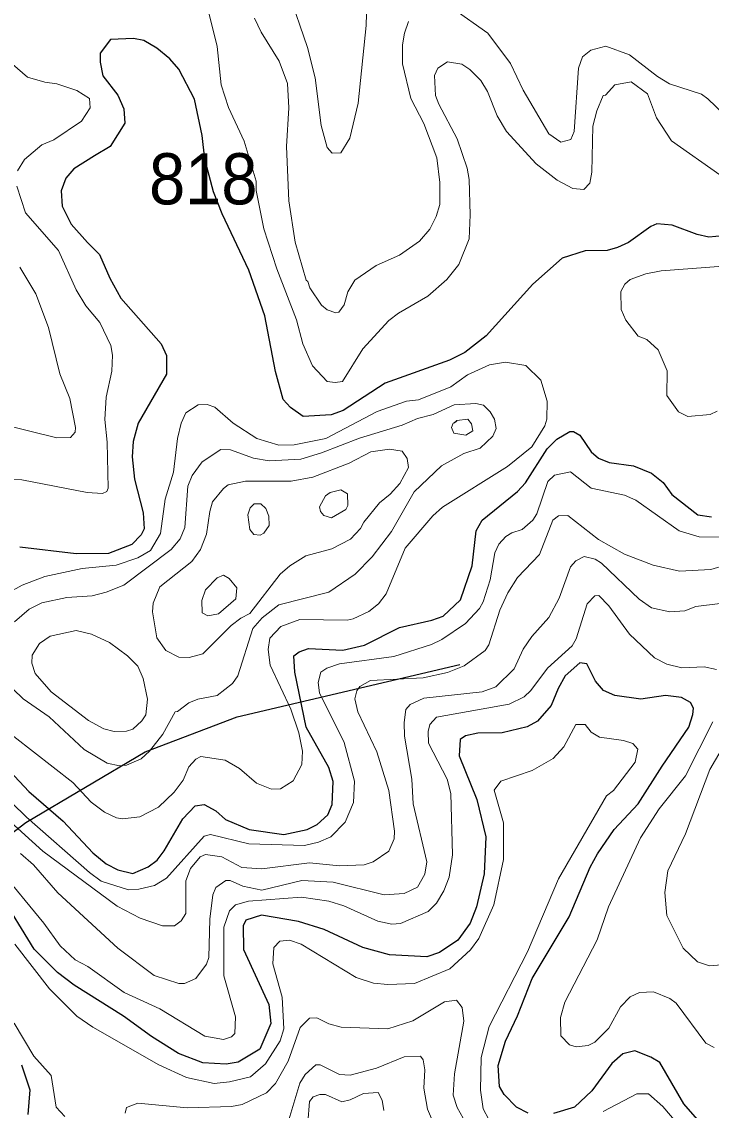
# Model space of a CAD drawing. Extents: x 673.3 to 698.5, y 6984.3 to 7012.3.
# Drawn here: x 679.596 to 680.675, y 6996.068 to 6997.77 of the extents above; entities that cross this region are included whole.
import ezdxf

# ---------------------------------------------------------------- set-up
doc = ezdxf.new("R2010")
doc.units = 0
doc.header["$LTSCALE"] = 0.032
for name, color, linetype, lineweight in [('1', 7, 'Continuous', 25), ('2', 7, 'Continuous', 13), ('26', 7, 'Continuous', 25)]:
    doc.layers.add(name, color=color, linetype=linetype, lineweight=lineweight)
doc.layers.add('21', color=7, linetype='Continuous')

msp = doc.modelspace()

# ---------------------------------------------------------------- linework, layer by layer
at = {"layer": '1'}
for points in [[(680.7042, 6997.4363), (680.6712, 6997.4331), (680.653, 6997.4373), (680.6137, 6997.4523), (680.59, 6997.4541), (680.5803, 6997.4501), (680.5455, 6997.425), (680.5285, 6997.4169), (680.5122, 6997.4127), (680.4777, 6997.4118), (680.4419, 6997.4004), (680.3957, 6997.36), (680.3227, 6997.2788), (680.2892, 6997.2527), (680.2656, 6997.241), (680.165, 6997.2049), (680.0989, 6997.1622), (680.0803, 6997.1553), (680.0363, 6997.1529), (680.0168, 6997.1668), (680.0053, 6997.1792), (679.9932, 6997.2234), (679.9767, 6997.3103), (679.9516, 6997.3817), (679.9099, 6997.4699), (679.8962, 6997.5041), (679.8829, 6997.5553), (679.8783, 6997.5921), (679.8664, 6997.6489), (679.8422, 6997.6963), (679.828, 6997.712), (679.8073, 6997.7289), (679.7871, 6997.7408), (679.7711, 6997.7441), (679.7353, 6997.7424), (679.719, 6997.7212), (679.7187, 6997.7071), (679.7229, 6997.6854), (679.7467, 6997.6554), (679.7561, 6997.6338), (679.7577, 6997.6116), (679.7345, 6997.5751), (679.7101, 6997.5605), (679.6775, 6997.5402), (679.665, 6997.5256), (679.6577, 6997.5057), (679.6597, 6997.4817), (679.6735, 6997.4536), (679.699, 6997.425), (679.718, 6997.4061)], [(679.718, 6997.4061), (679.734, 6997.369), (679.7511, 6997.3378), (679.8145, 6997.2663), (679.8229, 6997.2481), (679.8227, 6997.2191), (679.7783, 6997.1425), (679.7707, 6997.1136), (679.7692, 6997.0898), (679.7724, 6997.0546), (679.7863, 6997.0022), (679.7876, 6996.9772), (679.7828, 6996.9678), (679.7682, 6996.9527), (679.7317, 6996.9387), (679.6815, 6996.9378), (679.5932, 6996.9484)], [(679.5777, 6996.5983), (679.6071, 6996.5664), (679.6611, 6996.5198), (679.7075, 6996.4701), (679.7284, 6996.4533), (679.7465, 6996.4439), (679.7698, 6996.438), (679.7939, 6996.4486), (679.8082, 6996.4588), (679.8192, 6996.4735), (679.8483, 6996.5236), (679.8675, 6996.5437), (679.8818, 6996.5459), (679.8998, 6996.5361), (679.9152, 6996.5224), (679.952, 6996.5066), (680.0063, 6996.499), (680.0425, 6996.5068), (680.0582, 6996.5144), (680.0753, 6996.5299), (680.0819, 6996.5461), (680.0832, 6996.5817), (680.0767, 6996.6038), (680.0411, 6996.6669), (680.0232, 6996.753), (680.0219, 6996.7784), (680.03, 6996.7848), (680.045, 6996.7897), (680.0985, 6996.7872), (680.1327, 6996.795), (680.187, 6996.8226), (680.2379, 6996.8341), (680.2556, 6996.8404), (680.2826, 6996.8662), (680.3009, 6996.9191), (680.3069, 6996.974), (680.3165, 6996.9908), (680.372, 6997.0357), (680.3845, 6997.0492), (680.418, 6997.1021), (680.4332, 6997.1171), (680.4535, 6997.1292), (680.4595, 6997.1292), (680.4692, 6997.1237), (680.4869, 6997.0973), (680.4986, 6997.0878), (680.5154, 6997.0811), (680.5532, 6997.0756), (680.5814, 6997.0643), (680.5998, 6997.0494), (680.6134, 6997.031), (680.6541, 6996.9988), (680.6755, 6996.9957)], [(680.3885, 6996.0632), (680.37, 6996.0726), (680.3509, 6996.0923), (680.3437, 6996.1049), (680.3417, 6996.1376), (680.3528, 6996.1757), (680.3718, 6996.2155), (680.3945, 6996.2738), (680.4526, 6996.3705), (680.4855, 6996.4477), (680.4968, 6996.4686), (680.5231, 6996.5068), (680.5604, 6996.5468), (680.5982, 6996.6057), (680.6397, 6996.6667), (680.6463, 6996.6868), (680.6469, 6996.6967), (680.6422, 6996.7054), (680.6283, 6996.7131), (680.6031, 6996.7163), (680.5648, 6996.7107), (680.5242, 6996.7166), (680.5061, 6996.7243), (680.4938, 6996.7386), (680.4803, 6996.766), (680.4693, 6996.7674), (680.4466, 6996.7471), (680.4352, 6996.7274), (680.4247, 6996.7009), (680.4031, 6996.6765), (680.3868, 6996.6676), (680.3477, 6996.6578), (680.3099, 6996.6577), (680.2905, 6996.6536), (680.2823, 6996.6476), (680.2807, 6996.6219), (680.3084, 6996.5539), (680.3221, 6996.4956), (680.3198, 6996.4373), (680.3076, 6996.386), (680.2977, 6996.3604), (680.2786, 6996.3335), (680.2499, 6996.3142), (680.2301, 6996.3076), (680.1718, 6996.3107), (680.13, 6996.3222), (680.0696, 6996.3503), (680.0291, 6996.3631), (679.9715, 6996.3726), (679.9467, 6996.3652), (679.9427, 6996.3563), (679.9434, 6996.3191), (679.9828, 6996.2332), (679.9858, 6996.2035), (679.9689, 6996.1631), (679.935, 6996.143), (679.916, 6996.1398), (679.8797, 6996.142), (679.8416, 6996.1565), (679.7991, 6996.1831), (679.7555, 6996.2151), (679.6781, 6996.2634), (679.6522, 6996.2834), (679.6158, 6996.3199), (679.5612, 6996.4071)], [(680.668, 6996.0366), (680.632, 6996.0777), (680.5945, 6996.1425), (680.5805, 6996.151), (680.5556, 6996.1609), (680.5364, 6996.156), (680.5196, 6996.1408), (680.488, 6996.098), (680.4609, 6996.0724), (680.428, 6996.0625)], [(679.5956, 6996.139), (679.6087, 6996.0998), (679.6056, 6996.0611)]]:
    msp.add_lwpolyline(points, dxfattribs=at)
at = {"layer": '2'}
for points in [[(680.1365, 6997.8202), (680.1348, 6997.7644), (680.1226, 6997.6431), (680.1093, 6997.5879), (680.0952, 6997.5652), (680.082, 6997.5646), (680.0742, 6997.5735), (680.0647, 6997.6081), (680.0551, 6997.6827), (680.0433, 6997.7297), (679.9839, 6997.9036)], [(679.8808, 6997.818), (679.902, 6997.7316), (679.9084, 6997.6717), (679.9197, 6997.636), (679.9443, 6997.5834)], [(680.7078, 6997.6133), (680.6697, 6997.6499), (680.6596, 6997.6568), (680.6095, 6997.6732), (680.5906, 6997.6845), (680.5472, 6997.7183), (680.5102, 6997.7318), (680.4864, 6997.7256), (680.4736, 6997.7154), (680.4671, 6997.6976), (680.4605, 6997.5984), (680.4555, 6997.5862), (680.4394, 6997.5821), (680.4209, 6997.5949), (680.3807, 6997.6633), (680.3609, 6997.705), (680.3252, 6997.7523), (680.2709, 6997.7911)], [(680.2015, 6997.7705), (680.1949, 6997.7524), (680.1919, 6997.7341), (680.1918, 6997.7042), (680.2049, 6997.6504), (680.2252, 6997.6113), (680.2455, 6997.5576), (680.2504, 6997.5188), (680.2504, 6997.4846), (680.2447, 6997.4658), (680.2344, 6997.4458), (680.2183, 6997.4269), (680.1872, 6997.4049), (680.1506, 6997.3891), (680.1172, 6997.3663), (680.1066, 6997.348), (680.1005, 6997.3277), (680.0923, 6997.3158), (680.0875, 6997.3149), (680.0743, 6997.3195), (680.0651, 6997.3268), (680.0469, 6997.354), (680.0439, 6997.3639), (680.041, 6997.3661), (680.0241, 6997.4254), (680.0143, 6997.4902), (680.0103, 6997.5749), (680.0143, 6997.6358), (680.0119, 6997.6734), (679.999, 6997.7088), (679.9707, 6997.7541), (679.9605, 6997.7758)], [(679.5898, 6997.5371), (679.6003, 6997.5547), (679.6274, 6997.5779), (679.6463, 6997.5854), (679.6896, 6997.6148), (679.7031, 6997.6355), (679.7023, 6997.6503), (679.6826, 6997.6627), (679.6509, 6997.6731), (679.6323, 6997.6756), (679.6052, 6997.6835), (679.5819, 6997.7041)], [(679.9443, 6997.5834), (679.9628, 6997.5207), (679.963, 6997.5063), (679.9752, 6997.4464), (679.9951, 6997.384), (680.0263, 6997.3041), (680.0361, 6997.2663), (680.051, 6997.2319), (680.0741, 6997.2077), (680.0866, 6997.2058), (680.0979, 6997.2075), (680.1298, 6997.2588), (680.1703, 6997.303), (680.1854, 6997.3145), (680.2315, 6997.3408), (680.2614, 6997.3673), (680.2801, 6997.3903), (680.296, 6997.4306), (680.2977, 6997.4684), (680.2961, 6997.5236), (680.2929, 6997.5411), (680.2772, 6997.5872), (680.2485, 6997.6411), (680.2437, 6997.6547), (680.2422, 6997.6861), (680.2474, 6997.6978), (680.2622, 6997.7074), (680.2846, 6997.7041), (680.297, 6997.6958), (680.3147, 6997.6781), (680.3248, 6997.6613), (680.34, 6997.623), (680.3545, 6997.5986), (680.4009, 6997.5479), (680.4337, 6997.5227), (680.4586, 6997.5094), (680.4757, 6997.5079), (680.485, 6997.5177), (680.4883, 6997.5351), (680.4899, 6997.6067), (680.496, 6997.6309), (680.506, 6997.6549), (680.5094, 6997.6555), (680.5242, 6997.6715), (680.5495, 6997.6764), (680.5754, 6997.6576), (680.5891, 6997.6198), (680.6125, 6997.5839), (680.6884, 6997.5308)], [(679.5422, 6997.0542), (679.5963, 6997.0535), (679.6985, 6997.034), (679.7226, 6997.0323), (679.7291, 6997.0356), (679.7312, 6997.0408), (679.73, 6997.1129), (679.726, 6997.1481), (679.7281, 6997.183), (679.7373, 6997.2238), (679.7382, 6997.2487), (679.7358, 6997.2641), (679.7182, 6997.2997), (679.6966, 6997.3261), (679.6811, 6997.351), (679.6535, 6997.4126), (679.6022, 6997.4716), (679.5884, 6997.513)], [(679.5934, 6997.3863), (679.6181, 6997.3448), (679.6381, 6997.2919), (679.6558, 6997.2194), (679.6715, 6997.1811), (679.6803, 6997.1357), (679.6796, 6997.1282), (679.6724, 6997.1202), (679.6513, 6997.1195), (679.5601, 6997.1416)], [(680.6938, 6997.3878), (680.5964, 6997.3808), (680.5724, 6997.376), (680.548, 6997.3672), (680.5396, 6997.36), (680.5333, 6997.3481), (680.5338, 6997.3201), (680.5413, 6997.3033), (680.5607, 6997.2785), (680.5743, 6997.2734), (680.592, 6997.2573), (680.6062, 6997.2243), (680.6056, 6997.1854), (680.6237, 6997.16), (680.6383, 6997.1527), (680.6732, 6997.1557), (680.6842, 6997.1613)], [(679.5838, 6996.6525), (679.6761, 6996.5805), (679.7049, 6996.5494), (679.7255, 6996.5339), (679.7447, 6996.525), (679.7539, 6996.5234), (679.7812, 6996.5265), (679.8101, 6996.542), (679.8348, 6996.5653), (679.8488, 6996.5842), (679.8574, 6996.6048), (679.8686, 6996.6169), (679.8762, 6996.621), (679.9146, 6996.6153), (679.9369, 6996.6023), (679.9636, 6996.5792), (679.9872, 6996.5698), (680.001, 6996.5706), (680.021, 6996.583), (680.0343, 6996.6086), (680.0354, 6996.6292), (680.0297, 6996.6579), (680.017, 6996.6949), (679.985, 6996.7641), (679.9817, 6996.7884), (679.9844, 6996.806), (680.0018, 6996.8244), (680.0315, 6996.8351), (680.1053, 6996.8345), (680.1146, 6996.8364), (680.1394, 6996.8478), (680.1546, 6996.86), (680.1664, 6996.8757), (680.1959, 6996.9467), (680.2392, 6996.9975), (680.2545, 6997.0108), (680.3564, 6997.0744), (680.3942, 6997.1052), (680.4145, 6997.1383), (680.4176, 6997.1487), (680.4182, 6997.1767), (680.4085, 6997.2096), (680.385, 6997.2324), (680.3532, 6997.2376), (680.3278, 6997.2334), (680.2937, 6997.2179), (680.2673, 6997.1991), (680.2171, 6997.1788), (680.1981, 6997.1769), (680.1525, 6997.1604), (680.0718, 6997.1185), (680.0223, 6997.1087), (679.9986, 6997.1081), (679.9639, 6997.1182), (679.9272, 6997.1426), (679.8981, 6997.1673), (679.8864, 6997.1715), (679.8723, 6997.171), (679.8531, 6997.1584), (679.8458, 6997.1424), (679.8401, 6997.1184), (679.8334, 6997.0655), (679.8205, 6997.0236), (679.8131, 6996.9697), (679.7974, 6996.9434), (679.7779, 6996.9316), (679.7438, 6996.9205), (679.6908, 6996.915), (679.6323, 6996.9028), (679.5968, 6996.889), (679.5724, 6996.8753)], [(679.5827, 6996.7263), (679.5987, 6996.711), (679.6393, 6996.683), (679.694, 6996.6318), (679.7301, 6996.6105), (679.7494, 6996.6064), (679.76, 6996.6073), (679.7828, 6996.6172), (679.7959, 6996.6291), (679.817, 6996.6558), (679.8364, 6996.6907), (679.84, 6996.6912), (679.8574, 6996.705), (679.8719, 6996.7106), (679.9017, 6996.7166), (679.9259, 6996.7354), (679.9345, 6996.7473), (679.958, 6996.8212), (679.9724, 6996.8381), (679.9983, 6996.858), (680.0768, 6996.8782), (680.1181, 6996.9064), (680.1442, 6996.9334), (680.1749, 6996.9731), (680.2099, 6997.0349), (680.2527, 6997.0754), (680.2879, 6997.095), (680.3134, 6997.1033), (680.3331, 6997.1218), (680.3383, 6997.1339), (680.3357, 6997.1484), (680.3288, 6997.1599), (680.3184, 6997.1704), (680.3066, 6997.1731), (680.2729, 6997.1708), (680.2397, 6997.156), (680.2154, 6997.1495), (680.1916, 6997.1391), (680.1245, 6997.1187), (680.0654, 6997.0958), (680.033, 6997.0861), (679.9835, 6997.0837), (679.9587, 6997.0875), (679.9229, 6997.1006), (679.9076, 6997.1011), (679.8784, 6997.0819), (679.8627, 6997.0606), (679.8561, 6997.0436), (679.8513, 6996.9792), (679.844, 6996.9615), (679.83, 6996.945), (679.7559, 6996.8888), (679.7284, 6996.878), (679.7064, 6996.8724), (679.6668, 6996.8695), (679.6275, 6996.8612), (679.6077, 6996.8513), (679.585, 6996.8317)], [(680.6894, 6996.9639), (680.6562, 6996.9648), (680.6247, 6996.9738), (680.557, 6997.022), (680.539, 6997.03), (680.4872, 6997.0405), (680.4548, 6997.0663), (680.4299, 6997.0609), (680.4193, 6997.0509), (680.4019, 6997.0005), (680.396, 6996.9906), (680.3793, 6996.9759), (680.3629, 6996.9708), (680.3533, 6996.9649), (680.3428, 6996.953), (680.3365, 6996.9394), (680.3293, 6996.8973), (680.3183, 6996.8627), (680.3124, 6996.8525), (680.2902, 6996.8288), (680.2532, 6996.8039), (680.2372, 6996.7963), (680.1783, 6996.7775), (680.0933, 6996.7659), (680.0735, 6996.7593), (680.0641, 6996.7529)], [(680.4064, 6996.937), (680.4272, 6996.9907), (680.4361, 6996.9973), (680.4508, 6996.9979), (680.4985, 6996.9606), (680.539, 6996.9373), (680.5843, 6996.9205), (680.6253, 6996.911), (680.6744, 6996.9133), (680.6989, 6996.9206)], [(679.5735, 6996.5235), (679.6292, 6996.4729), (679.7453, 6996.387), (679.7816, 6996.368), (679.8162, 6996.3564), (679.8351, 6996.3562), (679.8454, 6996.3642), (679.853, 6996.3752), (679.8531, 6996.4264), (679.8604, 6996.4459), (679.8755, 6996.4643), (679.8838, 6996.4679), (679.909, 6996.4639), (679.9405, 6996.4475), (679.9717, 6996.4451), (680.0466, 6996.4548), (680.0932, 6996.4501), (680.1318, 6996.4516), (680.1461, 6996.4561), (680.1705, 6996.4729), (680.1787, 6996.4925), (680.1796, 6996.5042), (680.1706, 6996.5676), (680.1517, 6996.6281), (680.1221, 6996.6911), (680.1171, 6996.7111), (680.1202, 6996.7236), (680.1253, 6996.7303), (680.142, 6996.74), (680.2241, 6996.7439), (680.2625, 6996.7523), (680.2885, 6996.7626), (680.3211, 6996.7869), (680.3267, 6996.7958), (680.3444, 6996.8498), (680.3565, 6996.8769), (680.3718, 6996.9012), (680.4064, 6996.937)], [(680.3808, 6996.7888), (680.394, 6996.8086), (680.421, 6996.8383), (680.4369, 6996.8686), (680.4549, 6996.9175), (680.4631, 6996.9272), (680.4759, 6996.9336), (680.4935, 6996.9298), (680.5034, 6996.9233), (680.5622, 6996.8673), (680.5813, 6996.8535), (680.6101, 6996.8475), (680.6337, 6996.849), (680.6507, 6996.8556), (680.6891, 6996.8604)], [(680.6832, 6996.7572), (680.664, 6996.7611), (680.6288, 6996.7595), (680.6053, 6996.7655), (680.5863, 6996.7753), (680.5469, 6996.8122), (680.5148, 6996.8567), (680.4993, 6996.8726), (680.4928, 6996.8723), (680.4806, 6996.8597), (680.4638, 6996.8052), (680.4575, 6996.7941), (680.4188, 6996.7592), (680.3926, 6996.7242), (680.382, 6996.7142), (680.3586, 6996.7028), (680.2452, 6996.6826), (680.2349, 6996.6713), (680.2318, 6996.6601), (680.2326, 6996.6418), (680.2617, 6996.5855), (680.2674, 6996.5631), (680.2701, 6996.4674), (680.2651, 6996.4321), (680.2568, 6996.4107), (680.2449, 6996.3917), (680.2319, 6996.3785), (680.1888, 6996.36), (680.1751, 6996.359), (680.1535, 6996.3637), (680.1001, 6996.3872), (680.0767, 6996.3947), (680.0339, 6996.4012), (679.951, 6996.3945), (679.9308, 6996.389), (679.921, 6996.3795), (679.9124, 6996.3543), (679.9125, 6996.2779), (679.9304, 6996.2138), (679.9295, 6996.1879), (679.9246, 6996.1823), (679.9116, 6996.1782), (679.8824, 6996.1834), (679.812, 6996.2262), (679.7567, 6996.2518), (679.6997, 6996.2924), (679.6798, 6996.3031), (679.6565, 6996.3249), (679.6309, 6996.3602), (679.56, 6996.4457)], [(679.5943, 6996.4691), (679.6146, 6996.4514), (679.6526, 6996.4077), (679.7466, 6996.3211), (679.8032, 6996.2783), (679.8418, 6996.2661), (679.851, 6996.266), (679.8688, 6996.2737), (679.8853, 6996.2961), (679.8888, 6996.3067), (679.8906, 6996.3664), (679.8951, 6996.4049), (679.8998, 6996.4162), (679.9155, 6996.427), (679.9223, 6996.4272), (679.9421, 6996.4182), (679.9716, 6996.4118), (680.0343, 6996.4272), (680.0835, 6996.4247), (680.163, 6996.4045), (680.1946, 6996.4069), (680.2156, 6996.4169), (680.2268, 6996.437), (680.2301, 6996.4565), (680.2088, 6996.5472), (680.2064, 6996.5855), (680.1951, 6996.653), (680.1943, 6996.6742), (680.1973, 6996.6946), (680.2041, 6996.7026), (680.2252, 6996.7122), (680.3164, 6996.7221), (680.3379, 6996.7299), (680.3668, 6996.7581), (680.3808, 6996.7888)], [(680.0641, 6996.7529), (680.0598, 6996.7367), (680.0623, 6996.7207), (680.1004, 6996.6428), (680.1169, 6996.5822), (680.1154, 6996.5491), (680.1022, 6996.5185), (680.08, 6996.4955), (680.0603, 6996.4868), (680.0385, 6996.4818), (679.9514, 6996.4843), (679.8914, 6996.4988), (679.8814, 6996.4964), (679.8229, 6996.4305), (679.804, 6996.4193), (679.7795, 6996.4134), (679.763, 6996.4126), (679.7206, 6996.4262), (679.7024, 6996.4394), (679.6035, 6996.5261), (679.5339, 6996.5941)], [(680.7184, 6996.6791), (680.6726, 6996.6005), (680.6347, 6996.5003), (680.6072, 6996.4422), (680.6022, 6996.4085), (680.6055, 6996.3721), (680.6308, 6996.3214), (680.6534, 6996.2999), (680.6724, 6996.2937), (680.6907, 6996.2953)], [(679.5855, 6996.3273), (679.6394, 6996.2575), (679.6825, 6996.2151), (679.7076, 6996.1979), (679.8105, 6996.1386), (679.8539, 6996.119), (679.8972, 6996.1097), (679.9212, 6996.1121), (679.9542, 6996.12), (679.9776, 6996.1405), (680.0003, 6996.1762), (680.006, 6996.1953), (680.0037, 6996.2448), (679.9891, 6996.2966), (679.9905, 6996.3224), (679.9998, 6996.3323), (680.0151, 6996.3335), (680.0333, 6996.3277), (680.1196, 6996.2756), (680.1464, 6996.2665), (680.1688, 6996.2644), (680.2105, 6996.266), (680.2662, 6996.2891), (680.2983, 6996.3186), (680.3115, 6996.3361), (680.3349, 6996.3891), (680.3499, 6996.4601), (680.3498, 6996.5173), (680.3353, 6996.5681), (680.3456, 6996.5823), (680.3949, 6996.5992), (680.4274, 6996.6179), (680.4441, 6996.6363), (680.4629, 6996.6711), (680.4779, 6996.6713), (680.4871, 6996.6591), (680.5002, 6996.6512), (680.5379, 6996.6462)], [(680.6794, 6996.1659), (680.6665, 6996.1726), (680.6198, 6996.2354), (680.6101, 6996.2425), (680.5844, 6996.253), (680.5626, 6996.2521), (680.5481, 6996.2451), (680.5331, 6996.2293), (680.5145, 6996.1962), (680.4926, 6996.1742), (680.4822, 6996.169), (680.4637, 6996.1667), (680.4531, 6996.17), (680.4395, 6996.1842), (680.4391, 6996.2127), (680.4461, 6996.2369), (680.4963, 6996.3342), (680.5141, 6996.3859), (680.564, 6996.494), (680.5937, 6996.539), (680.6344, 6996.5907), (680.6773, 6996.6751)], [(680.5379, 6996.6462), (680.5523, 6996.6411), (680.5599, 6996.6327), (680.5559, 6996.6122), (680.5222, 6996.568), (680.511, 6996.5596), (680.4358, 6996.4299), (680.3877, 6996.3155), (680.3274, 6996.1985), (680.3148, 6996.1504), (680.3138, 6996.0993), (680.3183, 6996.0699), (680.3267, 6996.0534)], [(679.758, 6996.0634), (679.7603, 6996.0721), (679.7777, 6996.0787), (679.8552, 6996.0714), (679.9243, 6996.0738), (679.9412, 6996.0769), (679.9793, 6996.095), (679.993, 6996.1096), (680.0129, 6996.1444), (680.032, 6996.1972), (680.0466, 6996.212), (680.058, 6996.2122), (680.0766, 6996.203), (680.0959, 6996.1976), (680.1688, 6996.1952), (680.208, 6996.2077), (680.2578, 6996.2374), (680.2763, 6996.2399), (680.2854, 6996.2284), (680.288, 6996.2069), (680.2733, 6996.1249), (680.271, 6996.0912), (680.2775, 6996.0719), (680.2917, 6996.0468)], [(679.6636, 6996.0581), (679.6503, 6996.0724), (679.642, 6996.122), (679.6151, 6996.1522), (679.5842, 6996.2041)], [(680.2414, 6996.0447), (680.2309, 6996.0692), (680.2253, 6996.102), (680.2268, 6996.1311), (680.2244, 6996.1465), (680.2201, 6996.1525), (680.1944, 6996.1515), (680.1513, 6996.1336), (680.1102, 6996.1227), (680.0931, 6996.1235), (680.063, 6996.1386), (680.0563, 6996.1386), (680.0397, 6996.1236), (680.0315, 6996.1099), (680.0078, 6996.0317)], [(680.1625, 6996.0672), (680.16, 6996.0835), (680.1539, 6996.0953), (680.1308, 6996.0941), (680.11, 6996.0841), (680.0969, 6996.0811), (680.0712, 6996.0922), (680.0627, 6996.0924), (680.052, 6996.0885), (680.0463, 6996.0814), (680.0436, 6996.0482)], [(680.5058, 6996.0657), (680.5583, 6996.0933), (680.5767, 6996.0933), (680.5992, 6996.0736), (680.6322, 6996.0348)]]:
    msp.add_lwpolyline(points, dxfattribs=at)
for points in [[(680.2724, 6997.1424), (680.2771, 6997.1464), (680.2941, 6997.1487), (680.3001, 6997.1414), (680.3017, 6997.1303), (680.2909, 6997.1236), (680.2721, 6997.1266), (680.2687, 6997.1355), (680.2711, 6997.1423), (680.277, 6997.1453)], [(679.8217, 6996.7867), (679.8075, 6996.8068), (679.801, 6996.8472), (679.8018, 6996.861), (679.8125, 6996.8866), (679.8624, 6996.926), (679.8757, 6996.9449), (679.8854, 6996.9687), (679.8903, 6997.0044), (679.8949, 6997.0193), (679.9116, 6997.0403), (679.9193, 6997.0461), (679.9465, 6997.0518), (680.0177, 6997.0519), (680.0516, 6997.0581), (680.1082, 6997.0797), (680.1423, 6997.0974), (680.1718, 6997.1016), (680.1913, 6997.0987), (680.1993, 6997.087), (680.2014, 6997.0731), (680.1879, 6997.0481), (680.1728, 6997.0313), (680.1559, 6997.0176), (680.1314, 6996.9873), (680.1264, 6996.9775), (680.1108, 6996.9611), (680.0813, 6996.9457), (680.0408, 6996.9347), (680.0155, 6996.9192), (680.0004, 6996.906), (679.9532, 6996.8449), (679.9388, 6996.8376), (679.9237, 6996.8259), (679.8796, 6996.7814), (679.8581, 6996.7758), (679.8419, 6996.7765)], [(680.0785, 6997.0341), (680.0955, 6997.038), (680.1056, 6997.0319), (680.1063, 6997.0137), (680.1031, 6997.0073), (680.081, 6996.9941), (680.0688, 6996.9982), (680.0638, 6997.0043), (680.0623, 6997.0114), (680.0716, 6997.0288)], [(679.9779, 6997.0087), (679.9702, 6997.016), (679.9598, 6997.016), (679.9535, 6997.0101), (679.95, 6996.9989), (679.9531, 6996.976), (679.9592, 6996.968), (679.9692, 6996.9672), (679.9747, 6996.9702), (679.9831, 6996.9824), (679.9828, 6996.9968)], [(679.9312, 6996.8678), (679.9328, 6996.8846), (679.9207, 6996.8994), (679.9116, 6996.9044), (679.9018, 6996.9004), (679.8837, 6996.8817), (679.8782, 6996.865), (679.8786, 6996.8458), (679.8874, 6996.8411), (679.9041, 6996.8441)], [(679.7777, 6996.7624), (679.7615, 6996.7786), (679.7333, 6996.7993), (679.7054, 6996.8125), (679.6815, 6996.818), (679.6405, 6996.8091), (679.6242, 6996.7977), (679.6127, 6996.7797), (679.612, 6996.7669), (679.6172, 6996.751), (679.6421, 6996.7221), (679.7007, 6996.6772), (679.7247, 6996.6644), (679.7409, 6996.6602), (679.76, 6996.6608), (679.7702, 6996.6638), (679.7842, 6996.6768), (679.7904, 6996.6864), (679.7927, 6996.7109), (679.7863, 6996.743)]]:
    msp.add_lwpolyline(points, close=True, dxfattribs=at)
at = {"layer": '26'}
msp.add_lwpolyline([(679.4787, 6996.4235), (679.6027, 6996.5178), (679.7895, 6996.6283), (679.933, 6996.683), (680.2815, 6996.765)], dxfattribs=at)

# ---------------------------------------------------------------- texts
at = {"layer": '21', "width": 0.95}
msp.add_text('818', height=0.08, dxfattribs=at).set_placement((679.7954, 6997.4846))

doc.saveas('drawing.dxf')
